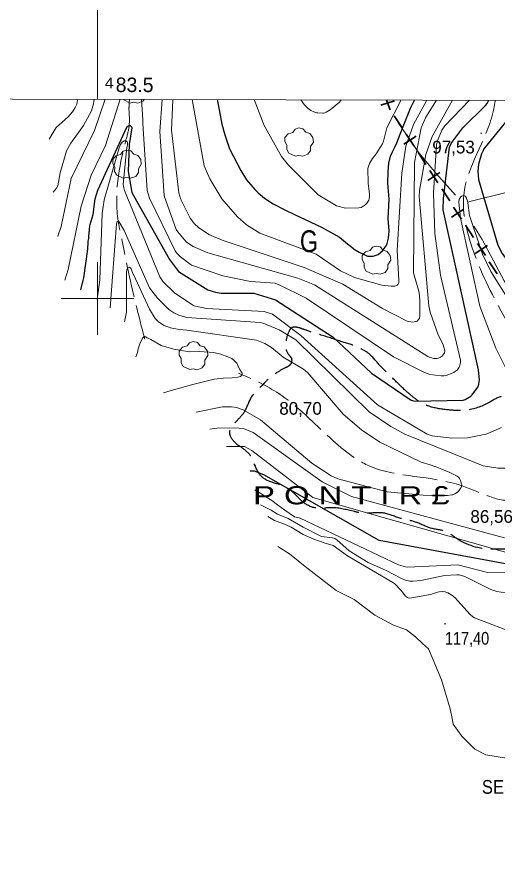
# Model space of a CAD drawing. Extents: x 480264 to 484872, y 4381275 to 4384491.
# Drawn here: x 483445 to 483776, y 4383600 to 4384194 of the extents above; entities that cross this region are included whole.
import ezdxf
from ezdxf.enums import TextEntityAlignment as Align

# ---------------------------------------------------------------- set-up
doc = ezdxf.new("R2010")
doc.units = 0
doc.header["$LTSCALE"] = 4
doc.linetypes.add('DOTTED', pattern=[1.5, 0.3, -1.2])
doc.linetypes.add('LONG_DASHED', pattern=[7.5, 6, -1.5])
for name, color, linetype, lineweight in [('1', 7, 'Continuous', 13), ('15', 7, 'LONG_DASHED', 13), ('2', 7, 'DOTTED', 13), ('29', 7, 'Continuous', 13), ('34', 7, 'Continuous', 35), ('38', 7, 'Continuous', 25), ('51', 7, 'Continuous', 13), ('7', 7, 'Continuous', 13), ('8', 7, 'Continuous', 25), ('9', 7, 'Continuous', 13)]:
    doc.layers.add(name, color=color, linetype=linetype, lineweight=lineweight)
doc.layers.add('31', color=7, linetype='Continuous')
doc.layers.add('5', color=7, linetype='Continuous')

msp = doc.modelspace()

# ---------------------------------------------------------------- linework, layer by layer
at = {"layer": '1'}
for p, q in [((483500, 4384137.24), (483500, 4384208.67)), ((483500, 4384025), (483500, 4383975)), ((483475, 4384000), (483525, 4384000))]:
    msp.add_line(p, q, dxfattribs=at)
msp.add_lwpolyline([(480523.1, 4384144.4), (484100.5, 4384135.8), (484095.6, 4381823.6), (480517.1, 4381832.1)], close=True, dxfattribs=at)
at = {"layer": '15'}
for points in [[(483521.62, 4384129.89), (483521.82, 4384135.14), (483521.87, 4384135.74), (483521.98, 4384137.19)], [(483774.04, 4384136.58), (483772.3, 4384127.81), (483752.25, 4384071.22), (483756.85, 4384038.64), (483803.38, 4383945.39), (483814.24, 4383897.42), (483787.76, 4383861.18), (483751.06, 4383870.8), (483688.08, 4383884.15), (483625.18, 4383934.22), (483597.18, 4383948.46)], [(483521.62, 4384129.89), (483521.76, 4384119.11), (483519.4, 4384108.53), (483514.19, 4384053.28), (483516.98, 4384039.65)], [(483532.45, 4383971.95), (483520.64, 4384021.11), (483516.98, 4384039.65)]]:
    msp.add_spline(points, degree=3, dxfattribs=at)
at = {"layer": '29'}
for points in [[(483522.57, 4384134.66), (483518.03, 4384136.78), (483517.8, 4384137.2)], [(483532.12, 4384137.17), (483531.25, 4384135.92), (483527.63, 4384134.58), (483524.86, 4384135.21), (483522.57, 4384134.66)]]:
    msp.add_lwpolyline(points, dxfattribs=at)
for points in [[(483636.26, 4384098.04), (483631.72, 4384100.16), (483630.31, 4384102.7), (483630.41, 4384105.68), (483629.04, 4384108.09), (483629.08, 4384110.84), (483631.24, 4384113.44), (483634.43, 4384114.44), (483636.08, 4384116.63), (483638.65, 4384117.46), (483641.51, 4384116.81), (483643.46, 4384114.54), (483646.27, 4384113.72), (483648.4, 4384110.87), (483648.64, 4384107.74), (483646.76, 4384104.59), (483646.76, 4384101.91), (483644.94, 4384099.3), (483641.32, 4384097.96), (483638.55, 4384098.59)], [(483517.71, 4384082.84), (483513.17, 4384084.96), (483511.76, 4384087.5), (483511.86, 4384090.48), (483510.49, 4384092.89), (483510.53, 4384095.64), (483512.69, 4384098.24), (483515.88, 4384099.24), (483517.53, 4384101.43), (483520.1, 4384102.26), (483522.96, 4384101.61), (483524.91, 4384099.34), (483527.72, 4384098.52), (483529.85, 4384095.67), (483530.09, 4384092.54), (483528.21, 4384089.39), (483528.21, 4384086.71), (483526.39, 4384084.1), (483522.77, 4384082.76), (483520, 4384083.39)], [(483689.53, 4384016.67), (483684.99, 4384018.79), (483683.58, 4384021.33), (483683.68, 4384024.31), (483682.31, 4384026.72), (483682.35, 4384029.47), (483684.51, 4384032.07), (483687.7, 4384033.07), (483689.35, 4384035.26), (483691.92, 4384036.09), (483694.78, 4384035.44), (483696.73, 4384033.17), (483699.54, 4384032.35), (483701.67, 4384029.5), (483701.91, 4384026.37), (483700.03, 4384023.22), (483700.03, 4384020.54), (483698.21, 4384017.93), (483694.59, 4384016.59), (483691.82, 4384017.22)], [(483563.48, 4383950.9), (483558.94, 4383953.02), (483557.53, 4383955.56), (483557.63, 4383958.54), (483556.26, 4383960.95), (483556.3, 4383963.7), (483558.46, 4383966.3), (483561.65, 4383967.3), (483563.3, 4383969.49), (483565.87, 4383970.32), (483568.73, 4383969.67), (483570.68, 4383967.4), (483573.49, 4383966.58), (483575.62, 4383963.73), (483575.86, 4383960.6), (483573.98, 4383957.45), (483573.98, 4383954.77), (483572.16, 4383952.16), (483568.54, 4383950.82), (483565.77, 4383951.45)]]:
    msp.add_lwpolyline(points, close=True, dxfattribs=at)
at = {"layer": '34'}
for p, q in [((483695.05, 4384133.07), (483704.55, 4384136.21)), ((483704.37, 4384125.83), (483709.83, 4384117.45)), ((483711.09, 4384106.34), (483719.47, 4384111.8)), ((483712.55, 4384113.26), (483718.01, 4384104.88)), ((483720.74, 4384100.69), (483726.2, 4384092.31)), ((483728.93, 4384088.12), (483734.39, 4384079.74)), ((483727.47, 4384081.21), (483735.85, 4384086.66)), ((483737.12, 4384075.56), (483742.57, 4384067.18)), ((483743.84, 4384056.07), (483752.22, 4384061.53)), ((483745.3, 4384062.99), (483750.76, 4384054.61)), ((483753.49, 4384050.42), (483758.95, 4384042.04)), ((483760.22, 4384030.93), (483768.6, 4384036.39)), ((483761.68, 4384037.85), (483767.14, 4384029.47)), ((483769.86, 4384025.28), (483775.32, 4384016.9))]:
    msp.add_line(p, q, dxfattribs=at)
msp.add_lwpolyline([(483699.09, 4384136.76), (483701, 4384131), (483701.64, 4384130.02)], dxfattribs=at)
at = {"layer": '38', "linetype": 'LONG_DASHED'}
for points in [[(483797.66, 4383951.17), (483793.94, 4383939.62), (483782.58, 4383933.86), (483772.51, 4383929.97), (483770.17, 4383928.58), (483754.92, 4383923.1), (483741.24, 4383923.21), (483727.68, 4383925.92), (483721.77, 4383928.84), (483715.08, 4383933.95), (483711.23, 4383937.31), (483702.92, 4383945.47), (483695.07, 4383953.18), (483686.77, 4383961.97), (483680.22, 4383965.97), (483667.51, 4383970.39), (483653.15, 4383975.04), (483642.98, 4383978.25), (483638.27, 4383979.87), (483633.14, 4383979.37), (483631.91, 4383977.45), (483629.73, 4383969.68), (483631.28, 4383961.7), (483633.49, 4383958.73), (483632.86, 4383954.55), (483629.24, 4383952.11), (483622.28, 4383948.05), (483615.53, 4383942.43), (483614.16, 4383940.81)], [(483850.38, 4383815.76), (483840.34, 4383813.09), (483834.51, 4383813.8), (483828.87, 4383812.7), (483821.91, 4383812.28), (483813.07, 4383814.28), (483802.92, 4383817.05), (483800.8, 4383817.91), (483795.39, 4383823.33), (483786.11, 4383827), (483779.48, 4383827.24), (483771.92, 4383827.1), (483746.93, 4383834.81), (483740.72, 4383838.99), (483730.16, 4383841.49), (483718.36, 4383846.12), (483708.26, 4383848.58), (483696.29, 4383852.18), (483684.4, 4383851.93), (483676.99, 4383853.05), (483661.51, 4383855.77), (483649.66, 4383855.69), (483640.48, 4383860.56), (483635.27, 4383865.78), (483625.84, 4383871.49), (483615.73, 4383875.12), (483610.77, 4383880), (483605.63, 4383891.18), (483601.86, 4383895.27), (483594.49, 4383900.86), (483591.05, 4383907.68), (483595.47, 4383915.22), (483601.34, 4383922.14), (483606.08, 4383931.96), (483614.16, 4383940.81)]]:
    msp.add_spline(points, degree=3, dxfattribs=at)
at = {"layer": '51'}
msp.add_line((483755.42, 4384066.52), (483782.35, 4384073.24), dxfattribs=at)
for points in [[(483746.49, 4384071.18), (483733.33, 4384086.17), (483721.2, 4384100.31), (483706.9, 4384121.47)], [(483896.23, 4383839.99), (483849.67, 4383906.12), (483810.74, 4383965.6), (483780.08, 4384012.22), (483764.86, 4384040.57), (483759.24, 4384049.75)]]:
    msp.add_lwpolyline(points, dxfattribs=at)
at = {"layer": '7'}
for p, q in [((483763.79, 4384113.87), (483764.79, 4384113.87)), ((483624.68, 4383934.22), (483625.68, 4383934.22)), ((483738.86, 4383775.74), (483739.86, 4383775.74))]:
    msp.add_line(p, q, dxfattribs=at)
at = {"layer": '8'}
for points in [[(483488.56, 4384005.93), (483489.57, 4384010.67), (483490.11, 4384012.39), (483490.54, 4384014.29), (483493.27, 4384034.01), (483493.33, 4384035.59), (483493.56, 4384037.18), (483493.63, 4384039.47), (483493.96, 4384041.24), (483493.99, 4384041.64), (483493.96, 4384042.97), (483493.98, 4384043.31), (483494.21, 4384044.42), (483494.24, 4384044.7), (483494.21, 4384045.65), (483494.23, 4384045.88), (483494.38, 4384046.65), (483494.39, 4384046.77), (483494.38, 4384047.96), (483494.59, 4384049.27), (483494.64, 4384050.04), (483494.81, 4384050.93), (483496.97, 4384057.72), (483498.42, 4384068.55), (483500.15, 4384074.53), (483520.48, 4384118.46), (483520.96, 4384118.8), (483521.24, 4384118.94), (483521.76, 4384119.11), (483522.26, 4384119.12), (483522.39, 4384119.09), (483522.52, 4384119.05), (483522.95, 4384118.77), (483523.29, 4384118.34), (483523.41, 4384118.07), (483523.53, 4384117.5), (483521.73, 4384105.97), (483521.17, 4384087.52), (483523.52, 4384072.96), (483549.44, 4384026.84), (483555.81, 4384018.64), (483575.96, 4384005.87), (483581.13, 4384004.32), (483585.2, 4384003.71), (483607.72, 4384003.58), (483622.57, 4383998.93), (483662.2, 4383973.39), (483688.82, 4383948.54), (483716.06, 4383929.86), (483716.91, 4383929.56), (483718.56, 4383929.19), (483751.96, 4383929.98), (483753.17, 4383930.42), (483756.06, 4383931.9), (483757.31, 4383932.87), (483757.94, 4383933.55), (483761.89, 4383938.76), (483762.18, 4383939.38), (483762.66, 4383940.83), (483763.1, 4383943.75), (483762.49, 4383950.86), (483738.08, 4384060.96), (483738.21, 4384068.95), (483742.53, 4384104.16), (483742.86, 4384105.1), (483743.63, 4384106.73), (483744.69, 4384108.4), (483751.69, 4384117.44), (483767.33, 4384132.87), (483768.28, 4384134.21), (483769.41, 4384136.2), (483769.51, 4384136.6)], [(483582.33, 4384137.05), (483584.01, 4384128.76), (483585.68, 4384120.11), (483587.68, 4384112.78), (483591, 4384103.12), (483598.66, 4384088.13), (483602.66, 4384081.8), (483608.32, 4384075.14), (483610.65, 4384072.81), (483614.97, 4384069.15), (483620.97, 4384065.15), (483628.96, 4384061.15), (483635.61, 4384057.82), (483642.94, 4384054.49), (483654.26, 4384049.16), (483666.57, 4384042.17), (483672.23, 4384037.51), (483677.56, 4384033.51), (483680.22, 4384031.84), (483683.55, 4384030.18), (483685.88, 4384029.18), (483689.88, 4384029.18), (483693.21, 4384030.18), (483696.2, 4384032.84), (483699.2, 4384036.84), (483700.53, 4384041.5), (483700.86, 4384046.5), (483700.2, 4384055.16), (483700.86, 4384068.48), (483699.95, 4384079.48), (483700.28, 4384087.3), (483700.61, 4384093.3), (483701.86, 4384098.12), (483702.86, 4384100.45), (483704.52, 4384103.79), (483706.19, 4384107.12), (483708.52, 4384113.11), (483710.52, 4384118.44), (483715.51, 4384131.1), (483718.24, 4384136.72)], [(483781.08, 4384121.49), (483766.18, 4384103.11), (483765.55, 4384102.04), (483764.45, 4384099.61), (483762.52, 4384092.41), (483762.03, 4384087.4), (483762.39, 4384081.99), (483775.72, 4384036.64), (483778.8, 4384030.92), (483800.4, 4384000.51), (483805.77, 4383995.58)], [(483847.11, 4383789.7), (483832.64, 4383795.9), (483807.9, 4383809.41), (483796.02, 4383814.29), (483693.92, 4383833.16), (483614.49, 4383878.44), (483608.15, 4383880.87), (483605.14, 4383880.98)]]:
    msp.add_lwpolyline(points, dxfattribs=at)
at = {"layer": '9'}
for points in [[(483466.63, 4384109.74), (483471.42, 4384117.8), (483479.8, 4384125.03), (483482.74, 4384128.55), (483484.57, 4384131.49), (483485.62, 4384133.95), (483486.25, 4384136.49), (483486.36, 4384137.28)], [(483505.23, 4384137.23), (483497.78, 4384115.78), (483481.79, 4384082.68), (483474.84, 4384049.61), (483472.7, 4384042.92), (483472.62, 4384042.75)], [(483477.49, 4384012.57), (483479.71, 4384019.86), (483488.72, 4384063.56), (483495.49, 4384084.86), (483505.36, 4384105.33), (483515.6, 4384137.21)], [(483497.62, 4384137.25), (483497.17, 4384134.07), (483495.71, 4384129.33), (483490.28, 4384119.22), (483481.55, 4384106.94)], [(483530.25, 4384137.17), (483531.25, 4384122.96), (483531.11, 4384120.44), (483534.08, 4384074.34), (483535.83, 4384069.1), (483553.35, 4384032.78), (483554.34, 4384031.43), (483557.02, 4384028.67), (483564.76, 4384022.9), (483586.25, 4384015.59), (483605.38, 4384011.56), (483622.32, 4384010.47), (483625.12, 4384009.46), (483643.68, 4384000.05), (483703.77, 4383959.64), (483725.14, 4383948.91), (483728.79, 4383947.66), (483736.71, 4383946.55), (483738.52, 4383946.65), (483740.04, 4383946.97), (483745.32, 4383948.97), (483746.66, 4383949.78), (483747.92, 4383950.83), (483748.7, 4383951.82), (483749.13, 4383952.52), (483749.36, 4383953.04), (483749.67, 4383954.07), (483749.95, 4383955.7), (483749.99, 4383957.5), (483736.25, 4384016.06), (483732.37, 4384044.82), (483731.49, 4384072.54), (483733.48, 4384105.75), (483734.23, 4384108.49), (483737.23, 4384115.98), (483739.23, 4384119.02), (483756.12, 4384136.63)], [(483744.51, 4384136.66), (483730.54, 4384111.61), (483726.13, 4384099.07), (483721.86, 4384074.26), (483721.54, 4384070.27), (483728.21, 4383994.87), (483729.01, 4383990.62), (483734.71, 4383974.96), (483737.76, 4383968.8), (483738.86, 4383965.75), (483739.05, 4383964.86), (483739.15, 4383963.72), (483739.02, 4383962.51), (483737.91, 4383960.81), (483737.62, 4383960.48), (483737.04, 4383959.98), (483736.19, 4383959.42), (483735.7, 4383959.18), (483734.97, 4383958.91), (483733.82, 4383958.7), (483731.72, 4383958.69), (483729.95, 4383958.97), (483728.8, 4383959.29), (483727.48, 4383959.85), (483649.48, 4384009.38), (483637.93, 4384013.96), (483575.87, 4384031.46), (483565.88, 4384035.69), (483561.96, 4384038.19), (483561.09, 4384038.89), (483555.37, 4384045.79), (483554.19, 4384047.6), (483545.87, 4384070.61), (483542.98, 4384115.04), (483544.43, 4384137.14)], [(483733.49, 4384136.68), (483726.17, 4384125), (483722.92, 4384117.55), (483718.29, 4384093.71), (483717.66, 4384017.71), (483721.48, 4384004.08), (483722.08, 4383998.75), (483722.02, 4383987.31), (483721.87, 4383986.76), (483721.72, 4383986.42), (483721.34, 4383985.76), (483720.87, 4383985.13), (483720.6, 4383984.84), (483720.09, 4383984.42), (483719.48, 4383984.11), (483719.08, 4383983.99), (483716.99, 4383983.74), (483715.71, 4383983.8), (483713.86, 4383984.18), (483713.3, 4383984.37), (483696.34, 4383993.08), (483668.88, 4384009.81), (483642.43, 4384021.37), (483585.72, 4384040.13), (483576.62, 4384044.15), (483569.47, 4384048.91), (483566.82, 4384051.44), (483563.81, 4384055.28), (483557.43, 4384068.2), (483555.89, 4384072.71), (483550.94, 4384115.86), (483551.89, 4384136.83), (483551.96, 4384137.12)], [(483565.11, 4384137.09), (483573.36, 4384091.43), (483577.26, 4384082.31), (483585.7, 4384068.52), (483596.36, 4384056.21), (483602.7, 4384050.64), (483611.81, 4384044.92), (483650.51, 4384030.48), (483667.28, 4384018.89), (483676.96, 4384014.47), (483695.77, 4384009.2), (483702.36, 4384008.38), (483704.87, 4384008.53), (483705.79, 4384008.84), (483706.39, 4384009.13), (483706.53, 4384009.23), (483706.66, 4384009.35), (483707.02, 4384009.85), (483707.43, 4384010.63), (483707.45, 4384010.8), (483707.43, 4384012.5), (483707.43, 4384012.54), (483706.46, 4384032.99), (483709.56, 4384086.23), (483712.38, 4384104.83), (483717.63, 4384119.95), (483726.75, 4384136.7)], [(483607.95, 4384136.98), (483614.88, 4384119.27), (483626.77, 4384097.74), (483631.44, 4384091.74), (483651.95, 4384071.48), (483664.66, 4384063.9), (483665.58, 4384063.58), (483670.79, 4384062.27), (483680.05, 4384062.38), (483681.63, 4384062.76), (483683.06, 4384063.52), (483684.24, 4384064.41), (483685.42, 4384065.6), (483686.39, 4384066.93), (483686.84, 4384067.8), (483687.06, 4384068.53), (483687.33, 4384070.25), (483687.34, 4384071.87), (483686.32, 4384079.36), (483686.25, 4384089.53), (483686.54, 4384090.79), (483687.35, 4384092.95), (483689.33, 4384096.51), (483691.97, 4384099.62), (483696.23, 4384106.5), (483696.98, 4384108.44), (483699.28, 4384117.62), (483709.1, 4384136.74)], [(483667.82, 4384136.84), (483667.43, 4384136.08), (483666.73, 4384135.19), (483660.21, 4384129.91), (483657.41, 4384128.27), (483656.6, 4384127.93), (483655.72, 4384127.71), (483655.1, 4384127.65), (483651.81, 4384127.78), (483650.91, 4384127.95), (483648.95, 4384128.59), (483646.96, 4384129.57), (483645.02, 4384130.93), (483642.33, 4384133.59), (483640.1, 4384136.91)], [(483481.55, 4384106.94), (483478.68, 4384101.59), (483474.35, 4384086.62), (483472.6, 4384077.47), (483471.78, 4384076.07), (483469.37, 4384073.1)], [(483499.65, 4383999.27), (483501.56, 4384012.81), (483503.21, 4384058.56), (483504.57, 4384067.83), (483514.94, 4384103.86), (483514.96, 4384103.88), (483515.88, 4384106.1), (483515.9, 4384106.12), (483516.92, 4384107.76), (483517.77, 4384108.27), (483518.42, 4384108.55), (483518.6, 4384108.59), (483518.77, 4384108.61), (483519.4, 4384108.53), (483519.92, 4384108.3), (483520.03, 4384108.22), (483520.13, 4384108.14), (483520.36, 4384107.79), (483520.58, 4384107.21), (483520.6, 4384107.06), (483520.55, 4384105.69), (483520.56, 4384105.67), (483520.56, 4384105.66), (483520.23, 4384104.08), (483520.23, 4384104.06), (483520.23, 4384104.05), (483519.9, 4384101.99), (483519.9, 4384101.98), (483517.72, 4384078.58), (483518.05, 4384076.16), (483518.59, 4384074.34), (483542.93, 4384014.96), (483545.23, 4384011.46), (483553.32, 4384003.68), (483565.99, 4383995.22), (483567.47, 4383994.63), (483575.14, 4383993.13), (483614.67, 4383990.96), (483620.53, 4383989.11), (483640.1, 4383974.41), (483692.91, 4383926.62), (483726.98, 4383906.34), (483730.53, 4383905.39), (483743.94, 4383903.57), (483754.85, 4383903.96), (483767.37, 4383906.39), (483769.39, 4383907.07)], [(483788.18, 4383938.15), (483774.25, 4383965.63), (483763.33, 4383994.68), (483749.91, 4384055.29), (483749.91, 4384055.31), (483748.82, 4384066.34), (483748.84, 4384066.37), (483749.15, 4384068.36), (483749.73, 4384069.33), (483750.27, 4384069.98), (483750.7, 4384070.35), (483750.97, 4384070.51), (483751.51, 4384070.74), (483752.04, 4384070.85), (483752.28, 4384070.86), (483752.62, 4384070.75), (483753.19, 4384070.45), (483753.37, 4384070.31), (483753.48, 4384070.16), (483754.14, 4384069.05), (483754.18, 4384068.99), (483754.25, 4384068.83), (483754.74, 4384067.34), (483754.76, 4384067.31), (483754.77, 4384067.29), (483755.16, 4384065.75), (483756.21, 4384057.11), (483765.23, 4384030.39), (483770.85, 4384018.5), (483797.94, 4383975.3)], [(483508.75, 4383993.54), (483513.04, 4384051.32), (483513.18, 4384052.1), (483513.33, 4384052.47), (483513.74, 4384053.01), (483514.19, 4384053.28), (483514.3, 4384053.29), (483514.4, 4384053.27), (483514.72, 4384052.98), (483518.34, 4384046.71), (483535.87, 4384007.31), (483541.49, 4383999.85), (483548.99, 4383992.43), (483552.46, 4383990.16), (483555.98, 4383988.52), (483561.56, 4383986.87), (483612.09, 4383983.43), (483614, 4383982.86), (483625.06, 4383978.39), (483636.52, 4383971.53), (483687.18, 4383921.76), (483701.95, 4383911.76), (483711.64, 4383906.46), (483765.71, 4383884.62), (483775.68, 4383883.09), (483781.21, 4383883.04)], [(483518.52, 4383983.76), (483519.91, 4383990.58), (483519.87, 4384018.13), (483520.17, 4384019.86), (483520.44, 4384020.46), (483520.71, 4384020.88), (483520.93, 4384021.07), (483521.43, 4384021.35), (483521.95, 4384021.45), (483522.09, 4384021.43), (483522.21, 4384021.39), (483522.61, 4384021.07), (483523.08, 4384020.46), (483523.15, 4384020.34), (483524.63, 4384016.49), (483524.64, 4384016.48), (483535.73, 4383992.53), (483539.72, 4383986.18), (483542.02, 4383983.82), (483545.95, 4383981.23), (483550.26, 4383979.66), (483556.14, 4383978.48), (483561.41, 4383978.22), (483609.59, 4383971.12), (483615.13, 4383968.88), (483619.72, 4383966.18), (483627.93, 4383959.46), (483641.81, 4383951.21), (483644.87, 4383948.65), (483669.19, 4383920.14), (483681.89, 4383909.46), (483694.43, 4383900.97), (483723.02, 4383887.04), (483729.08, 4383885.23), (483729.09, 4383885.22), (483732.43, 4383884.07), (483732.45, 4383884.06), (483737.18, 4383882.27), (483737.19, 4383882.26), (483737.2, 4383882.25), (483742.6, 4383880.02), (483742.62, 4383880), (483742.63, 4383879.99), (483747.64, 4383877.43), (483748.79, 4383876.47), (483749.24, 4383875.94), (483750.12, 4383874.56), (483750.8, 4383872.05), (483750.83, 4383871.46), (483750.81, 4383870.88), (483750.82, 4383870.73), (483750.82, 4383870.61), (483750.81, 4383870.56), (483750.72, 4383870.21), (483750.52, 4383869.74), (483749.9, 4383868.71), (483748.84, 4383867.36), (483747.94, 4383866.53), (483746.11, 4383865.37), (483744.63, 4383864.7), (483744, 4383864.53), (483741.17, 4383864.08), (483741.13, 4383864.07), (483736.14, 4383864.1), (483736.11, 4383864.09), (483732.69, 4383864.04), (483732.67, 4383864.03), (483730.11, 4383864.18), (483730.09, 4383864.18), (483724.26, 4383864.51), (483724.24, 4383864.51), (483699.5, 4383866.71), (483665.45, 4383875.55), (483660.91, 4383877.69), (483647.59, 4383886.44), (483612.3, 4383916.43), (483600.29, 4383923.22), (483595.71, 4383924.75), (483592.28, 4383925.24), (483586.01, 4383925.23), (483567.88, 4383921.63)], [(483526.44, 4383959.73), (483527.6, 4383962.83), (483527.99, 4383965.35), (483529.15, 4383968.65), (483529.54, 4383969.82), (483530.51, 4383971.56), (483530.9, 4383972.53), (483531.86, 4383973.5), (483532.06, 4383973.69), (483532.45, 4383973.69), (483533.03, 4383973.5), (483534.19, 4383972.72), (483536.71, 4383971.75), (483543.88, 4383967.49), (483552.61, 4383964.97), (483563.27, 4383963.22), (483570.25, 4383963.41), (483580.13, 4383962.83), (483584.98, 4383961.48), (483589.63, 4383959.73), (483592.54, 4383958.57), (483594.09, 4383957.21), (483595.84, 4383955.46), (483596.42, 4383954.49), (483596.81, 4383953.14), (483597.97, 4383951), (483599.13, 4383949.26), (483599.71, 4383948.48), (483599.52, 4383947.51), (483598.55, 4383946.15), (483596.61, 4383945.77), (483592.74, 4383945.18), (483586.53, 4383944.99), (483580.33, 4383944.41), (483564.82, 4383940.53), (483552.41, 4383937.04), (483545.43, 4383934.9)], [(483780.29, 4383834.89), (483674.95, 4383863.49), (483654.74, 4383873.54), (483607.16, 4383907.57), (483601.64, 4383909.97), (483600.32, 4383910.26), (483594.63, 4383910.91), (483582.29, 4383910.64), (483577.24, 4383909.86)], [(483769.39, 4383907.07), (483778.26, 4383911.12)], [(483814.14, 4383815.73), (483648.24, 4383862.82), (483606.37, 4383895.17), (483601.11, 4383897.94), (483588.85, 4383897.84)], [(483635.61, 4383849.45), (483628.95, 4383854.02), (483623.97, 4383857.68), (483619.97, 4383860.68), (483615.98, 4383863.34), (483614.32, 4383864.34), (483608.33, 4383868)], [(483654.26, 4383836.03), (483641.59, 4383842.37), (483631.28, 4383848.36), (483623.97, 4383851.36), (483619.64, 4383854.02), (483612.32, 4383857.68)], [(483672.24, 4383822.65), (483662.22, 4383829.73), (483656.89, 4383831.39), (483648.91, 4383834.06), (483641.59, 4383837.38), (483633.28, 4383842.37), (483629.95, 4383844.04), (483621.97, 4383847.03), (483617.31, 4383849.7)], [(483785.95, 4383810.79), (483768.51, 4383811.14), (483748.12, 4383816.41), (483713.84, 4383814.69), (483712.07, 4383815.03), (483707.32, 4383816.46), (483639.62, 4383848.58), (483638.97, 4383848.79), (483635.61, 4383849.45)], [(483654.26, 4383836.03), (483661.78, 4383835.06), (483663.37, 4383834.44), (483664.87, 4383833.57), (483673.38, 4383826.02), (483686.38, 4383817.99), (483698.42, 4383812.83), (483709.29, 4383806.9), (483712.11, 4383805.79), (483715.08, 4383805.19), (483717.41, 4383805.1), (483722.79, 4383805.65), (483738.91, 4383809.14), (483747.44, 4383809.53), (483749.16, 4383809.4), (483752.98, 4383808.43), (483770.96, 4383799.34), (483775.06, 4383797.96), (483781, 4383797.14)], [(483767.43, 4383685.56), (483759.83, 4383689.3), (483750.85, 4383698.29), (483744.86, 4383706.61), (483744.2, 4383710.6), (483742.87, 4383717.26), (483736.88, 4383737.22), (483730.56, 4383752.53), (483727.9, 4383758.52), (483723.91, 4383762.18), (483718.92, 4383766.84), (483712.93, 4383771.5), (483703.95, 4383774.82), (483690.98, 4383781.81), (483676.68, 4383792.46), (483664.37, 4383798.78), (483644.08, 4383814.42), (483632.11, 4383824.07), (483624.13, 4383829.06)], [(483789.72, 4383768.33), (483759.64, 4383779.8), (483758.59, 4383780.52), (483756.47, 4383782.29), (483746.41, 4383793.66), (483744.03, 4383795.49), (483741.24, 4383797.15), (483740.58, 4383797.39), (483739.47, 4383797.69), (483737.46, 4383797.95), (483735.32, 4383797.87), (483734.27, 4383797.64), (483729.43, 4383796.02), (483716.49, 4383793.54), (483714.59, 4383793.52), (483713.92, 4383793.65), (483713.47, 4383793.86), (483712.83, 4383794.28), (483712.23, 4383794.88), (483709.11, 4383798.78), (483704.63, 4383803.44), (483672.24, 4383822.65)], [(483781.62, 4383683.24), (483767.43, 4383685.56)]]:
    msp.add_lwpolyline(points, dxfattribs=at)

# ---------------------------------------------------------------- texts
at = {"layer": '2', "width": 1.1}
msp.add_text('4', height=7.5, rotation=359.862, dxfattribs=at).set_placement((483504.98, 4384144.73))
at = {"layer": '2'}
msp.add_text('83.5', height=10, rotation=359.862, dxfattribs=at).set_placement((483512.48, 4384142.21))
at = {"layer": '31', "width": 0.8}
msp.add_text('G', height=15, dxfattribs=at).set_placement((483645.63, 4384031.93), align=Align.CENTER)
at = {"layer": '5'}
for s, height, width, p in [('P O N T I R £', 12.49, 1.35, (483742.47, 4383858.09)), ('SES MOLETES', 9.5, 0.9, (483845.42, 4383658.61))]:
    msp.add_text(s, height=height, dxfattribs=dict(at, width=width)).set_placement(p, align=Align.RIGHT)
at = {"layer": '7'}
for s, p in [('97,53', (483730.58, 4384099.9)), ('80,70', (483625.18, 4383919.85)), ('86,56', (483756.83, 4383845.34))]:
    msp.add_text(s, height=8.75, dxfattribs=at).set_placement(p)
at = {"layer": '7', "width": 0.85}
msp.add_text('117,40', height=8.75, dxfattribs=at).set_placement((483739.36, 4383761.37))

doc.saveas('drawing.dxf')
